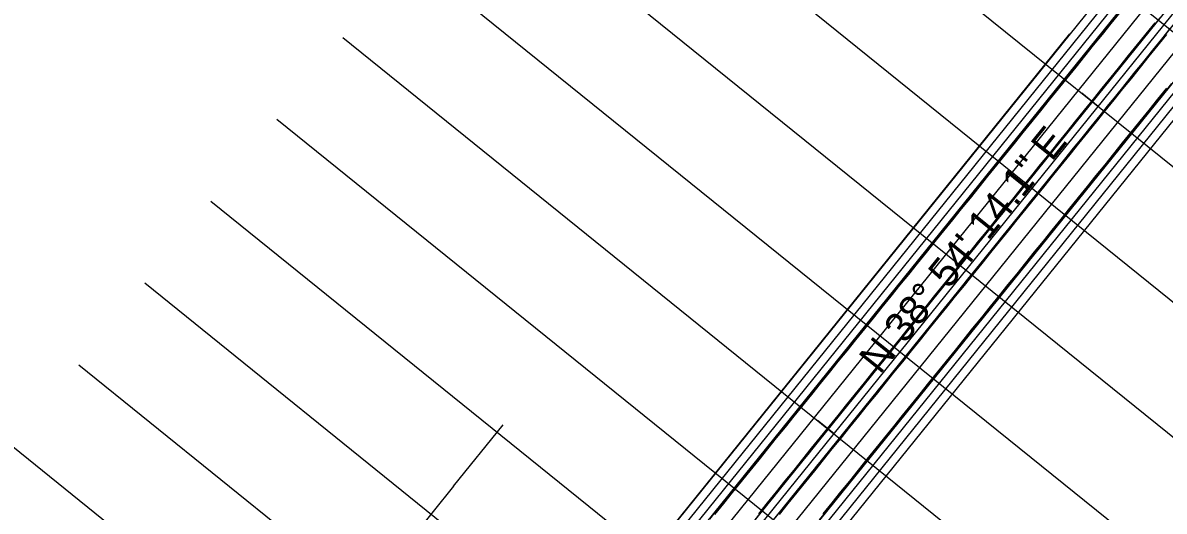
# Model space of a CAD drawing. Extents: x 2293233 to 2294507, y 892788 to 894229.
# Drawn here: x 2293687.7 to 2293959.1, y 893456.1 to 893572.2 of the extents above; entities that cross this region are included whole.
import ezdxf

# ---------------------------------------------------------------- set-up
doc = ezdxf.new("R2010")
doc.units = 0
for name, color, linetype in [('COGO Default Curve', 7, 'Continuous'), ('Prop EOT', 7, 'Continuous'), ('Prop Horizontal Alignment', 7, 'Continuous'), ('Prop Horizontal Alignment Direction Label', 7, 'Continuous'), ('Prop Paved Shoulder', 7, 'Continuous'), ('Prop Roadway Bridge', 7, 'Continuous'), ('Scratch_Level_4', 7, 'Continuous'), ('Scratch_Level_5', 7, 'Continuous')]:
    doc.layers.add(name, color=color, linetype=linetype)

msp = doc.modelspace()

# ---------------------------------------------------------------- linework, layer by layer
at = {"layer": 'COGO Default Curve'}
for p, q in [((2293758.37, 893332.69), (2294065.5, 893713.27)), ((2293767.71, 893325.15), (2294074.84, 893705.73))]:
    msp.add_line(p, q, dxfattribs=at)
for points in [[(2294073.94, 893697.86), (2293868.79, 893443.63), (2293792.2, 893348.66), (2293779.83, 893333.36), (2293770.79, 893322.25), (2293765.29, 893315.55), (2293760.6, 893309.91), (2293756.09, 893304.55), (2293751.76, 893299.48), (2293746.96, 893293.94), (2293742.34, 893288.69), (2293737.45, 893283.22), (2293732.75, 893278.03), (2293727.78, 893272.64), (2293722.77, 893267.28), (2293717.72, 893261.96), (2293712.86, 893256.92), (2293707.73, 893251.68), (2293702.8, 893246.71), (2293697.59, 893241.55), (2293692.58, 893236.66)], [(2294044.74, 893680.7), (2293954.06, 893568.41), (2293770.67, 893341.16), (2293761.43, 893329.77), (2293756.77, 893324.11), (2293752.51, 893318.98), (2293748.22, 893313.88), (2293744.11, 893309.05), (2293739.98, 893304.26), (2293735.81, 893299.49), (2293731.62, 893294.74), (2293727.39, 893290.03), (2293722.91, 893285.09), (2293718.62, 893280.44), (2293714.3, 893275.81), (2293709.95, 893271.21), (2293705.56, 893266.64), (2293701.15, 893262.1), (2293696.71, 893257.59), (2293692.23, 893253.11), (2293687.73, 893248.66), (2293683.19, 893244.24), (2293678.63, 893239.85)], [(2293680.14, 893237.74), (2293686.34, 893243.78), (2293692.26, 893249.64), (2293698.14, 893255.55), (2293703.96, 893261.51), (2293709.74, 893267.51), (2293715.47, 893273.56), (2293720.92, 893279.42), (2293726.55, 893285.56), (2293732.12, 893291.75), (2293737.87, 893298.24), (2293743.8, 893305.01), (2293749.89, 893312.08), (2293756.38, 893319.69), (2293763.26, 893327.84), (2293770.53, 893336.54), (2293778.4, 893346.03), (2293786.88, 893356.32), (2293796.39, 893367.93), (2293808.61, 893382.91), (2293822.69, 893400.24), (2293860.23, 893446.62), (2293932.89, 893536.61), (2294046.75, 893677.72)], [(2293687.14, 893261.63), (2293692.08, 893266.58), (2293696.99, 893271.57), (2293701.87, 893276.59), (2293706.71, 893281.65), (2293711.51, 893286.74), (2293716.29, 893291.86), (2293721.02, 893297.02), (2293725.73, 893302.2), (2293730.62, 893307.66), (2293735.48, 893313.16), (2293740.31, 893318.68), (2293745.1, 893324.23), (2293750.07, 893330.06), (2293755.02, 893335.92), (2293760.15, 893342.06), (2293765.46, 893348.48), (2293771.17, 893355.44), (2293778.96, 893365), (2293789.02, 893377.44), (2293934.91, 893558.24), (2293982.19, 893616.89)], [(2293948.5, 893574.65), (2293946.4, 893572.06), (2293944.31, 893569.46), (2293942.21, 893566.87), (2293940.12, 893564.28), (2293938.03, 893561.68), (2293935.93, 893559.09), (2293933.84, 893556.49), (2293931.75, 893553.9), (2293929.65, 893551.3), (2293927.56, 893548.71), (2293925.47, 893546.12), (2293923.37, 893543.52), (2293921.28, 893540.93), (2293919.18, 893538.33), (2293917.09, 893535.74), (2293915, 893533.14), (2293912.9, 893530.55), (2293910.81, 893527.96), (2293908.72, 893525.36), (2293906.62, 893522.77), (2293904.53, 893520.17), (2293902.44, 893517.58), (2293900.34, 893514.98), (2293898.25, 893512.39), (2293896.15, 893509.8), (2293894.06, 893507.2), (2293891.97, 893504.61), (2293889.87, 893502.01), (2293887.78, 893499.42), (2293885.69, 893496.82), (2293883.59, 893494.23), (2293881.5, 893491.64), (2293879.41, 893489.04), (2293877.31, 893486.45), (2293875.22, 893483.85), (2293873.12, 893481.26), (2293871.03, 893478.66), (2293868.94, 893476.07), (2293866.84, 893473.48), (2293864.75, 893470.88), (2293862.66, 893468.29), (2293860.56, 893465.69), (2293858.47, 893463.1), (2293856.38, 893460.5), (2293854.28, 893457.91), (2293852.19, 893455.32)], [(2293947.24, 893573.52), (2293945.14, 893570.92), (2293943.05, 893568.33), (2293940.96, 893565.73), (2293938.86, 893563.14), (2293936.77, 893560.54), (2293934.68, 893557.95), (2293932.59, 893555.35), (2293930.49, 893552.76), (2293928.4, 893550.16), (2293926.31, 893547.57), (2293924.21, 893544.97), (2293922.12, 893542.38), (2293920.03, 893539.78), (2293917.93, 893537.19), (2293915.84, 893534.6), (2293913.75, 893532), (2293911.65, 893529.41), (2293909.56, 893526.81), (2293907.47, 893524.22), (2293905.37, 893521.62), (2293903.28, 893519.03), (2293901.19, 893516.43), (2293899.09, 893513.84), (2293897, 893511.25), (2293894.91, 893508.65), (2293892.81, 893506.06), (2293890.72, 893503.46), (2293888.63, 893500.87), (2293886.53, 893498.27), (2293884.44, 893495.68), (2293882.35, 893493.09), (2293880.25, 893490.49), (2293878.16, 893487.9), (2293876.07, 893485.3), (2293873.97, 893482.71), (2293871.88, 893480.11), (2293869.78, 893477.52), (2293867.69, 893474.92), (2293865.6, 893472.33), (2293863.5, 893469.74), (2293861.41, 893467.14), (2293859.32, 893464.55), (2293857.22, 893461.95), (2293855.13, 893459.36), (2293853.04, 893456.76), (2293850.94, 893454.17)], [(2293958.04, 893573.37), (2293955.94, 893570.78), (2293953.85, 893568.18), (2293951.76, 893565.59), (2293949.67, 893562.99), (2293947.57, 893560.4), (2293945.48, 893557.8), (2293943.39, 893555.21), (2293941.29, 893552.61), (2293939.2, 893550.02), (2293937.11, 893547.42), (2293935.02, 893544.83), (2293932.92, 893542.23), (2293930.83, 893539.64), (2293928.74, 893537.04), (2293926.64, 893534.45), (2293924.55, 893531.85), (2293922.46, 893529.26), (2293920.36, 893526.66), (2293918.27, 893524.07), (2293916.18, 893521.47), (2293914.08, 893518.88), (2293911.99, 893516.29), (2293909.9, 893513.69), (2293907.8, 893511.1), (2293905.71, 893508.5), (2293903.62, 893505.91), (2293901.52, 893503.31), (2293899.43, 893500.72), (2293897.33, 893498.12), (2293895.24, 893495.53), (2293893.15, 893492.94), (2293891.05, 893490.34), (2293888.96, 893487.75), (2293886.87, 893485.15), (2293884.77, 893482.56), (2293882.68, 893479.96), (2293880.59, 893477.37), (2293878.49, 893474.78), (2293876.4, 893472.18), (2293874.31, 893469.59), (2293872.21, 893466.99), (2293870.12, 893464.4), (2293868.03, 893461.8), (2293865.93, 893459.21), (2293863.84, 893456.62), (2293861.74, 893454.02)], [(2293956.81, 893572.22), (2293954.72, 893569.63), (2293952.63, 893567.03), (2293950.53, 893564.44), (2293948.44, 893561.85), (2293946.35, 893559.25), (2293944.25, 893556.66), (2293942.16, 893554.06), (2293940.07, 893551.47), (2293937.97, 893548.87), (2293935.88, 893546.28), (2293933.78, 893543.69), (2293931.69, 893541.09), (2293929.6, 893538.5), (2293927.5, 893535.9), (2293925.41, 893533.31), (2293923.32, 893530.71), (2293921.22, 893528.12), (2293919.13, 893525.53), (2293917.04, 893522.93), (2293914.94, 893520.34), (2293912.85, 893517.74), (2293910.75, 893515.15), (2293908.66, 893512.55), (2293906.57, 893509.96), (2293904.47, 893507.37), (2293902.38, 893504.77), (2293900.29, 893502.18), (2293898.19, 893499.58), (2293896.1, 893496.99), (2293894.01, 893494.39), (2293891.91, 893491.8), (2293889.82, 893489.21), (2293887.73, 893486.61), (2293885.63, 893484.02), (2293883.54, 893481.42), (2293881.44, 893478.83), (2293879.35, 893476.23), (2293877.26, 893473.64), (2293875.16, 893471.05), (2293873.07, 893468.45), (2293870.98, 893465.86), (2293868.88, 893463.26), (2293866.79, 893460.67), (2293864.7, 893458.07), (2293862.6, 893455.48)], [(2293866.34, 893454.19), (2293868.44, 893456.78), (2293870.53, 893459.37), (2293872.63, 893461.97), (2293874.72, 893464.56), (2293876.82, 893467.15), (2293878.91, 893469.75), (2293881.01, 893472.34), (2293883.1, 893474.93), (2293885.19, 893477.53), (2293887.29, 893480.12), (2293889.38, 893482.71), (2293891.48, 893485.31), (2293893.57, 893487.9), (2293895.67, 893490.49), (2293897.76, 893493.09), (2293899.85, 893495.68), (2293901.95, 893498.28), (2293904.04, 893500.87), (2293906.14, 893503.46), (2293908.23, 893506.06), (2293910.32, 893508.65), (2293912.42, 893511.25), (2293914.51, 893513.84), (2293916.61, 893516.43), (2293918.7, 893519.03), (2293920.79, 893521.62), (2293922.89, 893524.22), (2293924.98, 893526.81), (2293927.07, 893529.4), (2293929.17, 893532), (2293931.26, 893534.59), (2293933.36, 893537.19), (2293935.45, 893539.78), (2293937.54, 893542.38), (2293939.64, 893544.97), (2293941.73, 893547.56), (2293943.82, 893550.16), (2293945.92, 893552.75), (2293948.01, 893555.35), (2293950.11, 893557.94), (2293952.2, 893560.53), (2293954.29, 893563.13), (2293956.39, 893565.72), (2293958.48, 893568.32), (2293960.57, 893570.91)], [(2293867.6, 893455.3), (2293869.69, 893457.9), (2293871.79, 893460.49), (2293873.88, 893463.09), (2293875.97, 893465.68), (2293878.07, 893468.27), (2293880.16, 893470.87), (2293882.25, 893473.46), (2293884.35, 893476.06), (2293886.44, 893478.65), (2293888.53, 893481.25), (2293890.63, 893483.84), (2293892.72, 893486.43), (2293894.82, 893489.03), (2293896.91, 893491.62), (2293899, 893494.22), (2293901.1, 893496.81), (2293903.19, 893499.41), (2293905.28, 893502), (2293907.38, 893504.59), (2293909.47, 893507.19), (2293911.56, 893509.78), (2293913.66, 893512.38), (2293915.75, 893514.97), (2293917.85, 893517.57), (2293919.94, 893520.16), (2293922.03, 893522.75), (2293924.13, 893525.35), (2293926.22, 893527.94), (2293928.31, 893530.54), (2293930.41, 893533.13), (2293932.5, 893535.73), (2293934.59, 893538.32), (2293936.69, 893540.91), (2293938.78, 893543.51), (2293940.88, 893546.1), (2293942.97, 893548.7), (2293945.06, 893551.29), (2293947.16, 893553.89), (2293949.25, 893556.48), (2293951.34, 893559.07), (2293953.44, 893561.67), (2293955.53, 893564.26), (2293957.62, 893566.86), (2293959.72, 893569.45)], [(2293877.15, 893454.03), (2293879.24, 893456.62), (2293881.33, 893459.22), (2293883.43, 893461.81), (2293885.52, 893464.4), (2293887.62, 893467), (2293889.71, 893469.59), (2293891.81, 893472.19), (2293893.9, 893474.78), (2293896, 893477.37), (2293898.09, 893479.97), (2293900.19, 893482.56), (2293902.28, 893485.16), (2293904.37, 893487.75), (2293906.47, 893490.34), (2293908.56, 893492.94), (2293910.66, 893495.53), (2293912.75, 893498.12), (2293914.84, 893500.72), (2293916.94, 893503.31), (2293919.03, 893505.91), (2293921.13, 893508.5), (2293923.22, 893511.1), (2293925.31, 893513.69), (2293927.41, 893516.28), (2293929.5, 893518.88), (2293931.59, 893521.47), (2293933.69, 893524.07), (2293935.78, 893526.66), (2293937.88, 893529.25), (2293939.97, 893531.85), (2293942.06, 893534.44), (2293944.16, 893537.04), (2293946.25, 893539.63), (2293948.35, 893542.23), (2293950.44, 893544.82), (2293952.53, 893547.41), (2293954.63, 893550.01), (2293956.72, 893552.6), (2293958.81, 893555.2), (2293960.91, 893557.79)], [(2293878.01, 893455.47), (2293880.11, 893458.06), (2293882.2, 893460.66), (2293884.29, 893463.25), (2293886.39, 893465.84), (2293888.48, 893468.44), (2293890.57, 893471.03), (2293892.67, 893473.63), (2293894.76, 893476.22), (2293896.85, 893478.82), (2293898.95, 893481.41), (2293901.04, 893484), (2293903.13, 893486.6), (2293905.23, 893489.19), (2293907.32, 893491.79), (2293909.42, 893494.38), (2293911.51, 893496.98), (2293913.6, 893499.57), (2293915.7, 893502.16), (2293917.79, 893504.76), (2293919.88, 893507.35), (2293921.98, 893509.95), (2293924.07, 893512.54), (2293926.16, 893515.14), (2293928.26, 893517.73), (2293930.35, 893520.32), (2293932.45, 893522.92), (2293934.54, 893525.51), (2293936.63, 893528.11), (2293938.73, 893530.7), (2293940.82, 893533.3), (2293942.91, 893535.89), (2293945.01, 893538.48), (2293947.1, 893541.08), (2293949.19, 893543.67), (2293951.29, 893546.27), (2293953.38, 893548.86), (2293955.48, 893551.46), (2293957.57, 893554.05), (2293959.66, 893556.64)]]:
    msp.add_lwpolyline(points, dxfattribs=at)
at = {"layer": 'Prop EOT'}
for p, q in [((2293753.7, 893336.46), (2294060.83, 893717.04)), ((2293753.7, 893336.46), (2294060.83, 893717.04)), ((2293772.37, 893321.38), (2294079.51, 893701.97))]:
    msp.add_line(p, q, dxfattribs=at)
at = {"layer": 'Prop Horizontal Alignment'}
for p, q in [((2293763.04, 893328.92), (2294070.17, 893709.5)), ((2293763.04, 893328.92), (2294070.17, 893709.5)), ((2293943.34, 893552.34), (2293939.45, 893555.48)), ((2293880.54, 893474.52), (2293876.65, 893477.66))]:
    msp.add_line(p, q, dxfattribs=at)
at = {"layer": 'Prop Paved Shoulder'}
for p, q in [((2293752.14, 893337.71), (2294059.27, 893718.29)), ((2293773.93, 893320.13), (2294081.06, 893700.71))]:
    msp.add_line(p, q, dxfattribs=at)
at = {"layer": 'Prop Roadway Bridge'}
for p, q in [((2293967.85, 893608.19), (2293839.83, 893449.55)), ((2293864.73, 893429.45), (2293992.76, 893588.1))]:
    msp.add_line(p, q, dxfattribs=at)
at = {"layer": 'Scratch_Level_4'}
for p, q in [((2293708.32, 893261.12), (2294130.82, 893784.65)), ((2293842.31, 893666), (2294075.77, 893477.59)), ((2293826.61, 893646.54), (2294060.07, 893458.14)), ((2293810.91, 893627.09), (2294044.37, 893438.68)), ((2293795.21, 893607.63), (2294028.67, 893419.23)), ((2293779.51, 893588.18), (2294012.97, 893399.77)), ((2293763.81, 893568.72), (2293997.27, 893380.32)), ((2293748.11, 893549.27), (2293981.57, 893360.86)), ((2293732.41, 893529.81), (2293965.87, 893341.41)), ((2293716.71, 893510.36), (2293950.17, 893321.95)), ((2293701.01, 893490.9), (2293934.47, 893302.5)), ((2293685.31, 893471.45), (2293918.77, 893283.04))]:
    msp.add_line(p, q, dxfattribs=at)
at = {"layer": 'Scratch_Level_5'}
for p, q in [((2293750.59, 893338.97), (2293936.67, 893569.56)), ((2293790.14, 893462.04), (2293801.92, 893476.63)), ((2293790.14, 893462.04), (2293743.04, 893403.68))]:
    msp.add_line(p, q, dxfattribs=at)

# ---------------------------------------------------------------- texts
at = {"layer": 'Prop Horizontal Alignment Direction Label'}
msp.add_text('N 38%%d 54\' 14.1" E', height=7, rotation=51.0961, dxfattribs=at).set_placement((2293891.48, 893488.4))

doc.saveas('drawing.dxf')
